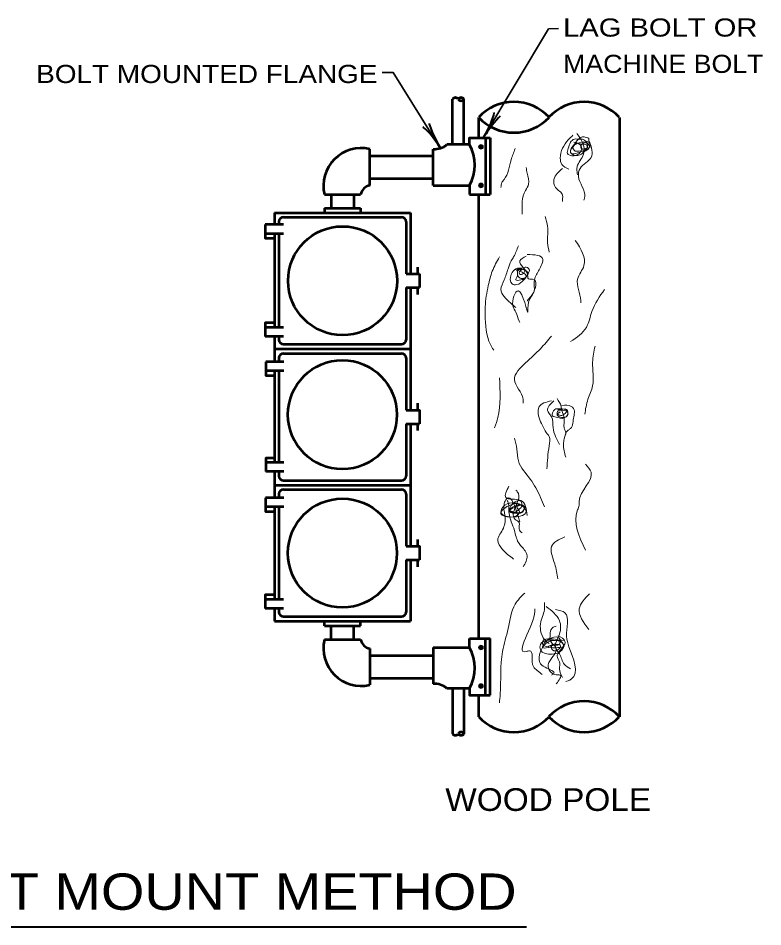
# Model space of a CAD drawing. Extents: x -370 to 486, y -203 to 341.
# Drawn here: x -214.9 to -116.5, y -9.6 to 110.5 of the extents above; entities that cross this region are included whole.
import ezdxf
from ezdxf.enums import TextEntityAlignment as Align

# ---------------------------------------------------------------- set-up
doc = ezdxf.new("R2010")
doc.units = 0
doc.header["$LTSCALE"] = 0.96
doc.layers.add('1', color=7, linetype='Continuous', lineweight=53)

msp = doc.modelspace()

# ---------------------------------------------------------------- hatches: boundary and pattern name
at = {"layer": '1'}
for points in [[(-153.4248, 93.5229, 1), (-154.0248, 93.5229, 1)], [(-153.4248, 88.4273, 1), (-154.0248, 88.4273, 1)], [(-153.4248, 27.3411, 1), (-154.0248, 27.3411, 1)], [(-153.4248, 22.2455, 1), (-154.0248, 22.2455, 1)]]:
    msp.add_hatch(color=256, dxfattribs=at).paths.add_polyline_path(points)

# ---------------------------------------------------------------- linework, layer by layer
at = {"layer": '1', "lineweight": 35}
for p, q in [((-153.327, 94.841), (-144.8055, 109.142)), ((-144.8055, 109.142), (-143.4878, 109.1573))]:
    msp.add_line(p, q, dxfattribs=at)
at = {"layer": '1'}
for p, q in [((-157.4734, 93.8253), (-157.4734, 99.8253)), ((-155.9734, 93.8253), (-155.9734, 99.8253)), ((-154.0234, 94.7253), (-154.0234, 97.4253)), ((-135.4234, 97.4253), (-135.4234, 18.1943)), ((-155.2234, 93.8253), (-158.2234, 93.8253)), ((-153.1234, 94.7253), (-153.1234, 87.2253)), ((-152.5234, 94.7253), (-152.5234, 87.2253)), ((-168.4234, 88.4253), (-168.4234, 93.2253)), ((-160.0234, 88.4253), (-160.0234, 93.2253)), ((-168.4234, 92.3253), (-160.0234, 92.3253)), ((-168.4234, 89.3253), (-160.0234, 89.3253)), ((-174.4234, 87.2253), (-169.6234, 87.2253)), ((-173.5234, 87.2253), (-173.5234, 85.4253)), ((-170.5234, 87.2253), (-170.5234, 85.4253)), ((-155.2234, 87.2253), (-152.5234, 87.2253)), ((-154.0234, 28.5431), (-154.0234, 87.2253)), ((-174.4234, 85.4253), (-169.6234, 85.4253)), ((-174.4234, 85.4253), (-174.4234, 84.8253)), ((-169.6234, 85.4253), (-169.6234, 84.8253)), ((-181.0234, 84.8253), (-163.0234, 84.8253)), ((-181.0234, 84.8253), (-181.0234, 83.2413)), ((-179.8234, 84.2253), (-164.2234, 84.2253)), ((-163.0234, 84.8253), (-163.0234, 76.7253)), ((-179.8234, 83.2413), (-182.2234, 83.2413)), ((-180.4234, 83.6253), (-180.4234, 83.2413)), ((-163.6234, 83.6253), (-163.6234, 76.7253)), ((-179.8234, 82.0413), (-182.2234, 82.0413)), ((-181.0234, 82.0413), (-181.0234, 69.6562)), ((-180.4234, 82.0413), (-180.4234, 69.6562)), ((-162.1234, 77.6253), (-162.1234, 76.7253)), ((-163.6234, 76.7253), (-161.8234, 76.7253)), ((-161.8234, 76.7253), (-161.8234, 74.9253)), ((-163.6234, 74.9253), (-163.6234, 68.0253)), ((-163.6234, 74.9253), (-161.8234, 74.9253)), ((-163.0234, 74.9253), (-163.0234, 58.7253)), ((-162.1234, 74.9253), (-162.1234, 74.0253)), ((-179.8234, 69.6562), (-182.2234, 69.6562)), ((-179.8234, 68.4562), (-182.2234, 68.4562)), ((-181.0234, 68.4562), (-181.0234, 65.1105)), ((-180.4234, 68.4562), (-180.4234, 68.0253)), ((-179.8234, 67.4253), (-164.2234, 67.4253)), ((-181.0234, 66.8253), (-163.0234, 66.8253)), ((-179.8234, 66.2253), (-164.2234, 66.2253)), ((-179.7735, 65.1105), (-182.1735, 65.1105)), ((-180.4234, 65.6253), (-180.4234, 65.1105)), ((-163.6234, 65.6253), (-163.6234, 58.7253)), ((-179.7735, 63.9105), (-182.1735, 63.9105)), ((-181.0234, 63.9105), (-181.0234, 51.7917)), ((-180.4234, 63.9105), (-180.4234, 51.7917)), ((-162.1234, 59.6253), (-162.1234, 58.7253)), ((-163.6234, 56.9253), (-161.8234, 56.9253)), ((-163.6234, 56.9253), (-163.6234, 50.0253)), ((-163.0234, 56.9253), (-163.0234, 40.7253)), ((-162.1234, 56.9253), (-162.1234, 56.0253)), ((-179.7735, 51.7917), (-182.1735, 51.7917)), ((-179.7735, 50.5917), (-182.1735, 50.5917)), ((-181.0234, 50.5917), (-181.0234, 47.1425)), ((-180.4234, 50.5917), (-180.4234, 50.0253)), ((-179.8234, 49.4253), (-164.2234, 49.4253)), ((-181.0234, 48.8253), (-163.0234, 48.8253)), ((-179.8234, 48.2253), (-164.2234, 48.2253)), ((-179.7935, 47.1425), (-182.1935, 47.1425)), ((-180.4234, 47.6253), (-180.4234, 47.1425)), ((-163.6234, 47.6253), (-163.6234, 40.7253)), ((-179.7935, 45.9425), (-182.1935, 45.9425)), ((-181.0234, 45.9425), (-181.0234, 33.7055)), ((-180.4234, 45.9425), (-180.4234, 33.7055)), ((-162.1234, 41.6253), (-162.1234, 40.7253)), ((-163.6234, 38.9253), (-161.8234, 38.9253)), ((-163.6234, 38.9253), (-163.6234, 32.0253)), ((-163.0234, 38.9253), (-163.0234, 30.8253)), ((-162.1234, 38.9253), (-162.1234, 38.0253)), ((-179.8251, 33.7055), (-182.2251, 33.7055)), ((-179.8251, 32.5055), (-182.2251, 32.5055)), ((-181.0234, 32.5055), (-181.0234, 30.8253)), ((-180.4234, 32.5055), (-180.4234, 32.0253)), ((-179.8234, 31.4253), (-164.2234, 31.4253)), ((-181.0234, 30.8253), (-163.0234, 30.8253)), ((-174.4234, 30.1943), (-174.4234, 30.7943)), ((-174.4234, 30.1943), (-169.6234, 30.1943)), ((-173.5234, 28.3943), (-173.5234, 30.1943)), ((-170.5234, 28.3943), (-170.5234, 30.1943)), ((-169.6234, 30.1943), (-169.6234, 30.7943)), ((-174.4234, 28.3943), (-169.6234, 28.3943)), ((-155.2234, 27.3431), (-155.2234, 28.5431)), ((-155.2234, 28.5431), (-152.5234, 28.5431)), ((-153.1234, 21.0431), (-153.1234, 28.5431)), ((-152.5234, 21.0431), (-152.5234, 28.5431)), ((-168.4234, 27.1943), (-168.4234, 22.3943)), ((-160.0234, 27.3431), (-155.2234, 27.3431)), ((-160.0234, 27.3431), (-160.0234, 22.5431)), ((-168.4234, 26.2943), (-160.0234, 26.2943)), ((-168.4234, 23.2943), (-160.0234, 23.2943)), ((-155.2234, 21.9431), (-158.2234, 21.9431)), ((-157.4734, 21.9431), (-157.4734, 15.9431)), ((-155.9734, 21.9431), (-155.9734, 15.9431)), ((-154.0234, 18.1943), (-154.0234, 21.0431))]:
    msp.add_line(p, q, dxfattribs=at)
at = {"layer": '1', "lineweight": 40}
msp.add_line((-234.6348, -9.5781), (-147.6889, -9.5781), dxfattribs=at)
at = {"layer": '1', "lineweight": 35}
msp.add_lwpolyline([(-159.1411, 93.4542), (-165.313, 103.3413), (-166.7889, 103.3413)], dxfattribs=at)
at = {"layer": '1'}
for points in [[(-155.2234, 93.8253), (-155.2234, 94.7253), (-152.5234, 94.7253)], [(-160.0234, 88.4253), (-155.2234, 88.4253), (-155.2234, 87.2253)], [(-182.2234, 83.2413), (-182.2234, 81.4413), (-181.0234, 81.4413)], [(-181.0234, 70.2562), (-182.2234, 70.2562), (-182.2234, 68.4562)], [(-182.1735, 65.1105), (-182.1735, 63.3105), (-181.0234, 63.3105)], [(-163.6234, 58.7253), (-161.8234, 58.7253), (-161.8234, 56.9253)], [(-180.9735, 52.3917), (-182.1735, 52.3917), (-182.1735, 50.5917)], [(-182.1935, 47.1425), (-182.1935, 45.3425), (-180.9935, 45.3425)], [(-163.6234, 40.7253), (-161.8234, 40.7253), (-161.8234, 38.9253)], [(-181.0251, 34.3055), (-182.2251, 34.3055), (-182.2251, 32.5055)], [(-155.2234, 21.9431), (-155.2234, 21.0431), (-152.5234, 21.0431)]]:
    msp.add_lwpolyline(points, dxfattribs=at)
at = {"layer": '1', "lineweight": 13}
for centre in [(-153.7248, 93.5229), (-153.7248, 88.4273), (-153.7248, 27.3411), (-153.7248, 22.2455)]:
    msp.add_circle(centre, 0.3, dxfattribs=at)
at = {"layer": '1'}
for centre in [(-172.0159, 75.8182), (-172.0296, 58.1258), (-172.0301, 39.8281)]:
    msp.add_circle(centre, 7.2, dxfattribs=at)
for centre, radius, start, end in [((-157.0984, 99.5841), 0.4459, 32.74583, 147.25417), ((-156.3484, 99.5841), 0.4459, 32.74583, 147.25417), ((-156.3484, 100.0651), 0.4459, 212.74583, 327.25417), ((-149.3734, 93.1113), 6.3555, 42.97503, 137.02497), ((-140.0876, 93.1113), 6.3555, 42.97503, 137.02497), ((-149.3734, 101.7577), 6.3555, 222.97503, 317.02497), ((-159.869, 95.762), 2.5414, 266.51631, 310.35359), ((-160.3163, 91.1253), 5.7643, 332.0697, 27.9303), ((-169.5568, 88.3587), 4.9969, 76.89015, 193.10985), ((-168.0832, 86.8851), 1.5774, 102.45679, 167.54321), ((-179.8234, 83.6253), 0.6, 90, 180), ((-164.2234, 83.6253), 0.6, 0, 90), ((-179.8234, 68.0253), 0.6, 180, 270), ((-164.2234, 68.0253), 0.6, 270, 0), ((-179.8234, 65.6253), 0.6, 90, 180), ((-164.2234, 65.6253), 0.6, 0, 90), ((-179.8234, 50.0253), 0.6, 180, 270), ((-164.2234, 50.0253), 0.6, 270, 0), ((-179.8234, 47.6253), 0.6, 90, 180), ((-164.2234, 47.6253), 0.6, 0, 90), ((-179.8234, 32.0253), 0.6, 180, 270), ((-164.2234, 32.0253), 0.6, 270, 0), ((-169.5568, 27.2609), 4.9969, 166.89015, 283.10985), ((-168.0832, 28.7345), 1.5774, 192.45679, 257.54321), ((-160.3163, 24.6431), 5.7643, 332.0697, 27.9303), ((-159.869, 20.0064), 2.5414, 49.64641, 93.48369), ((-140.0876, 13.8803), 6.3555, 42.97503, 137.02497), ((-149.3734, 22.5267), 6.3555, 222.97503, 317.02497), ((-140.0876, 22.5267), 6.3555, 222.97503, 317.02497), ((-157.0984, 16.1843), 0.4459, 212.74583, 327.25417), ((-156.3484, 15.7033), 0.4459, 32.74583, 147.25417), ((-156.3484, 16.1843), 0.4459, 212.74583, 327.25417)]:
    msp.add_arc(centre, radius, start, end, dxfattribs=at)
at = {"layer": '1', "lineweight": 40}
for centre, major_axis, ratio, start_param, end_param in [((-152.9415, 96.1356), (-0.9359, -1.9367), 0.122415, 0.89635335, 3.14159265), ((-152.4206, 95.8661), (1.26, 1.7028), 0.07063, 6.28230741, 8.55970261), ((-160.1158, 94.3894), (1.2937, -1.7185), 0.122415, 0.89635335, 3.14159265), ((-159.6377, 94.7293), (-0.9373, 1.8996), 0.07063, 6.28230741, 8.55970261)]:
    msp.add_ellipse(centre, major_axis=major_axis, ratio=ratio, start_param=start_param, end_param=end_param, dxfattribs=at)
at = {"layer": '1', "lineweight": 13}
for points in [[(-141.5677, 95.0657), (-142.1946, 94.4386), (-143.2395, 92.0347), (-143.0305, 91.1985), (-142.0902, 90.5714)], [(-139.5825, 94.2296), (-140.5229, 93.6025), (-140.4184, 93.2889), (-139.896, 93.2889), (-139.1646, 93.6025), (-139.478, 93.8115), (-139.896, 94.125), (-141.0453, 93.916), (-141.5677, 93.4979), (-141.2543, 92.9753), (-140.7318, 92.9753), (-140.0005, 92.9753), (-139.478, 93.2889), (-139.3735, 93.707), (-139.478, 94.125), (-139.478, 94.6476), (-139.7915, 94.7522), (-140.3139, 94.8567), (-140.5229, 94.7522), (-141.0453, 94.3341), (-141.5677, 93.4979), (-141.8812, 93.0799), (-141.7767, 92.6618), (-140.6274, 92.4527), (-140.0005, 92.9753), (-139.687, 93.3934), (-139.7915, 93.8115), (-140.6274, 93.916), (-140.8363, 94.0205), (-141.7767, 93.2889), (-141.8812, 92.7663), (-140.5229, 92.8708), (-139.5825, 93.707), (-140.3139, 94.5431), (-140.7318, 94.5431), (-141.3588, 94.5431), (-141.8812, 94.125), (-142.1946, 93.2889), (-142.2991, 92.6618), (-141.4632, 92.3482), (-140.6274, 92.7663), (-140.4184, 93.4979), (-140.9408, 94.0205), (-141.4632, 94.125)], [(-141.0453, 95.2748), (-140.5229, 94.5431), (-140.2094, 93.8115), (-140.1049, 92.7663), (-140.9408, 91.094), (-141.0453, 90.5714), (-140.9408, 89.8398)], [(-139.3735, 94.2296), (-139.1646, 92.1392), (-140.6274, 90.6759), (-140.8363, 89.6307), (-140.0005, 86.9132), (-140.1049, 86.4951)], [(-149.1952, 93.2889), (-149.7176, 91.8256), (-150.658, 89.2126), (-150.9714, 88.7946), (-151.0759, 88.1674)], [(-147.7324, 90.7804), (-147.6279, 90.0488), (-147.4189, 88.5855), (-147.8369, 87.7494), (-148.2548, 86.2861), (-148.2548, 85.2409), (-148.2548, 84.6138)], [(-142.926, 90.6759), (-144.0754, 89.2126), (-143.8664, 88.1674), (-142.926, 87.1222), (-142.926, 86.7042), (-142.926, 86.2861)], [(-145.2247, 84.3002), (-144.9113, 83.046), (-144.9113, 80.8511), (-144.7023, 79.5968)], [(-141.2543, 81.1646), (-140.1049, 77.82), (-140.9408, 76.0432), (-140.5229, 73.2212), (-140.5229, 72.9076)], [(-148.7772, 80.433), (-149.4041, 78.9697), (-149.7176, 78.4471), (-150.1355, 77.4019), (-150.658, 75.9387), (-151.0759, 74.6844), (-149.8221, 72.9076), (-149.0907, 72.2805)], [(-147.6279, 79.2833), (-145.5382, 78.6562), (-145.7471, 77.82), (-146.4785, 76.4613), (-146.6875, 75.7296), (-146.6875, 74.4754), (-147.4189, 73.0121), (-147.5234, 71.6534), (-148.7772, 74.4754), (-149.5086, 72.4895), (-149.0907, 71.6534), (-148.6727, 70.5037), (-148.5683, 70.2946)], [(-151.2849, 78.9697), (-152.2252, 77.0884), (-152.7477, 75.207), (-153.1656, 72.385), (-153.1656, 70.8172), (-152.2252, 66.95), (-152.0163, 66.6364)], [(-147.7324, 79.0743), (-148.5683, 78.4471), (-147.5234, 76.3567), (-147.5234, 76.1477), (-146.8965, 76.0432), (-146.8965, 74.0573), (-147.3144, 73.5347), (-147.6279, 73.1166)], [(-148.0458, 77.4019), (-148.6727, 76.8793), (-148.5683, 76.6703), (-148.1503, 76.7748), (-147.9413, 77.0884), (-148.0458, 77.2974), (-148.5683, 77.2974), (-148.7772, 77.2974), (-148.8817, 76.9839), (-148.6727, 76.2522), (-148.0458, 76.1477), (-147.5234, 76.8793), (-148.1503, 77.2974), (-148.7772, 77.4019), (-148.8817, 77.2974), (-148.8817, 76.5658), (-149.0907, 75.9387), (-148.4638, 75.9387), (-147.7324, 76.3567), (-147.4189, 76.8793), (-147.3144, 77.1929), (-147.7324, 77.611), (-148.2548, 77.5065), (-148.6727, 77.5065), (-149.0907, 77.4019), (-149.7176, 76.6703), (-149.6131, 75.4161), (-148.9862, 75.3116), (-148.0458, 75.9387), (-147.7324, 76.4613), (-148.1503, 76.8793), (-148.5683, 77.0884), (-149.0907, 77.2974)], [(-137.3883, 74.6844), (-139.0601, 71.7579), (-139.7915, 69.6675), (-141.8812, 67.7862)], [(-144.3888, 68.5178), (-145.8516, 66.8455), (-147.8369, 64.9641), (-149.2997, 62.7692), (-148.1503, 60.1562), (-148.1503, 59.6336)], [(-138.6421, 67.159), (-138.9556, 65.0687), (-138.9556, 61.9331), (-139.5825, 60.1562), (-140.0005, 58.1704)], [(-151.2849, 62.9783), (-151.4938, 57.7523), (-151.9118, 56.3935)], [(-143.6574, 60.2608), (-143.135, 59.2156), (-143.0305, 58.693), (-142.7171, 57.6478), (-142.7171, 56.3935), (-142.5081, 55.6619), (-142.6126, 55.2438)], [(-144.3888, 59.9472), (-146.0606, 59.111), (-146.1651, 58.2749), (-145.3292, 56.1845), (-145.2247, 55.9755), (-144.7023, 55.2438), (-144.7023, 53.9896), (-145.0158, 50.9585)], [(-144.0754, 59.9472), (-144.9113, 58.693), (-144.3888, 57.8568), (-144.1799, 56.3935), (-143.8664, 55.2438), (-143.344, 54.1986)], [(-143.2395, 58.4839), (-143.6574, 58.0659), (-143.344, 57.8568), (-142.8216, 57.7523), (-142.1946, 58.1704), (-142.6126, 58.693), (-142.8216, 58.693), (-143.4485, 58.693), (-143.6574, 58.3794), (-143.344, 58.0659), (-142.7171, 58.1704), (-142.4036, 58.693), (-143.2395, 58.902), (-143.9709, 58.7975), (-144.2844, 57.9613), (-143.553, 57.7523), (-143.2395, 57.6478), (-142.2991, 58.0659), (-142.4036, 58.7975), (-143.344, 58.7975), (-143.4485, 58.7975), (-143.553, 58.7975)], [(-143.0305, 59.3201), (-141.7767, 59.2156), (-141.3588, 58.5884), (-141.4632, 57.8568), (-141.8812, 56.289), (-142.1946, 56.08), (-142.7171, 54.9303), (-142.8216, 54.1986), (-142.5081, 52.5263)], [(-149.2997, 55.0348), (-148.9862, 53.5715), (-148.7772, 52.0037), (-147.2099, 49.5998), (-145.8516, 47.1958), (-145.3292, 45.9416)], [(-139.896, 51.5856), (-139.1646, 50.5405), (-140.7318, 46.6732), (-140.7318, 46.1506), (-140.9408, 45.5235), (-139.896, 40.193)], [(-150.0311, 48.6591), (-150.449, 47.1958), (-148.4638, 46.7778), (-147.6279, 44.7919)], [(-149.0907, 48.1365), (-148.7772, 47.7184), (-148.9862, 46.3597), (-149.1952, 44.2693), (-148.6727, 43.8512), (-148.6727, 43.0151), (-148.2548, 42.4925)], [(-148.5683, 43.9557), (-150.3445, 46.9868), (-150.658, 46.3597), (-150.5535, 44.7919), (-150.7624, 43.1196), (-151.4938, 41.5518), (-150.8669, 40.2976), (-149.4041, 39.0433)], [(-148.4638, 46.1506), (-149.8221, 45.419), (-149.2997, 45.21), (-148.0458, 45.5235), (-147.9413, 45.9416), (-148.4638, 46.1506), (-149.1952, 46.0461), (-149.9266, 45.419), (-149.2997, 45.21), (-148.6727, 45.628), (-148.3593, 45.9416), (-148.4638, 46.6732), (-149.6131, 46.2552), (-149.8221, 45.9416), (-149.9266, 45.3145), (-148.9862, 45.1054), (-148.1503, 45.3145), (-148.1503, 46.1506), (-148.6727, 46.2552), (-148.8817, 46.3597), (-149.2997, 46.3597), (-151.0759, 45.0009), (-148.6727, 45.1054), (-148.6727, 45.419), (-148.9862, 45.9416), (-148.9862, 46.3597), (-149.2997, 46.4642), (-150.5535, 46.1506), (-151.0759, 45.21), (-147.7324, 45.3145), (-148.2548, 46.0461), (-149.1952, 46.4642), (-150.1355, 46.3597)], [(-150.24, 46.7778), (-150.0311, 46.1506), (-150.0311, 45.7326), (-149.7176, 43.9557), (-149.2997, 42.806), (-148.7772, 41.2382), (-148.3593, 40.7156), (-147.6279, 39.4614), (-148.1503, 37.9981)], [(-142.6126, 41.9699), (-144.3888, 40.7156), (-143.9709, 38.4162), (-143.553, 36.4303)], [(-147.9413, 34.549), (-149.1952, 33.0857), (-150.1355, 29.8456), (-150.8669, 26.8145), (-151.1804, 21.1705), (-151.2849, 20.0208)], [(-139.3735, 34.4445), (-140.7318, 32.4586), (-139.478, 29.7411)], [(-146.583, 32.4586), (-146.583, 32.145), (-147.7324, 26.8145), (-147.3144, 26.9191), (-146.792, 24.8287), (-146.2696, 24.3061), (-145.6427, 23.7835)], [(-145.3292, 33.2948), (-145.3292, 32.3541), (-145.8516, 30.4727), (-145.1202, 28.1733), (-144.7023, 27.8597)], [(-145.1202, 32.7722), (-143.344, 30.8908), (-143.344, 29.114), (-143.8664, 27.3371), (-143.344, 26.501), (-142.7171, 25.1422), (-141.8812, 24.5151)], [(-143.8664, 32.3541), (-142.6126, 31.936), (-142.4036, 28.8004), (-142.0902, 27.4417), (-141.7767, 23.1564), (-142.1946, 22.9473), (-142.5081, 22.8428)], [(-143.7619, 30.1592), (-144.2844, 29.9501), (-144.5978, 28.4869), (-144.5978, 28.3823), (-143.8664, 27.4417), (-144.4933, 25.7694), (-144.8068, 25.2468), (-143.9709, 23.7835), (-143.2395, 23.679), (-143.7619, 22.5293)], [(-143.8664, 27.8597), (-144.3888, 27.5462), (-144.2844, 27.0236), (-143.344, 27.2326), (-143.2395, 27.6507), (-143.6574, 27.7552), (-144.0754, 27.7552), (-144.8068, 27.4417), (-144.4933, 27.3371), (-143.553, 27.3371), (-142.7171, 27.5462), (-143.135, 28.0688), (-143.8664, 28.2778), (-145.8516, 27.7552), (-145.8516, 27.0236), (-142.8216, 27.3371), (-142.8216, 27.7552), (-143.344, 28.2778), (-144.5978, 28.4869), (-145.5382, 28.1733), (-145.5382, 27.7552), (-143.6574, 27.6507), (-143.553, 27.6507), (-143.2395, 28.3823), (-144.4933, 28.5914), (-145.5382, 27.3371), (-144.3888, 27.4417)], [(-143.553, 28.9049), (-142.6126, 28.1733), (-143.553, 26.501), (-143.6574, 26.1874), (-143.344, 25.4558), (-143.344, 24.5151), (-142.926, 23.3654)], [(-142.7171, 28.2778), (-145.0158, 27.9643), (-145.8516, 26.8145), (-145.9561, 25.3513), (-145.2247, 24.7242), (-144.0754, 23.888), (-144.3888, 23.679)]]:
    msp.add_spline(points, degree=3, dxfattribs=at)

# ---------------------------------------------------------------- texts
at = {"layer": '1'}
for s, width, p in [('LAG BOLT OR', 1.2, (-142.8616, 108.0994)), ('MACHINE BOLT', 1.1, (-142.8616, 103.2994))]:
    msp.add_text(s, height=2.4, dxfattribs=dict(at, width=width)).set_placement(p)
for s, height, width, p in [('BOLT MOUNTED FLANGE', 2.4, 1.15, (-189.9558, 101.9623)), ('WOOD POLE', 3, 1.1, (-144.8294, 5.7436)), ('POST MOUNT METHOD', 4.8, 1.15, (-190.6266, -7.3253))]:
    msp.add_text(s, height=height, dxfattribs=dict(at, width=width)).set_placement(p, align=Align.CENTER)

doc.saveas('drawing.dxf')
